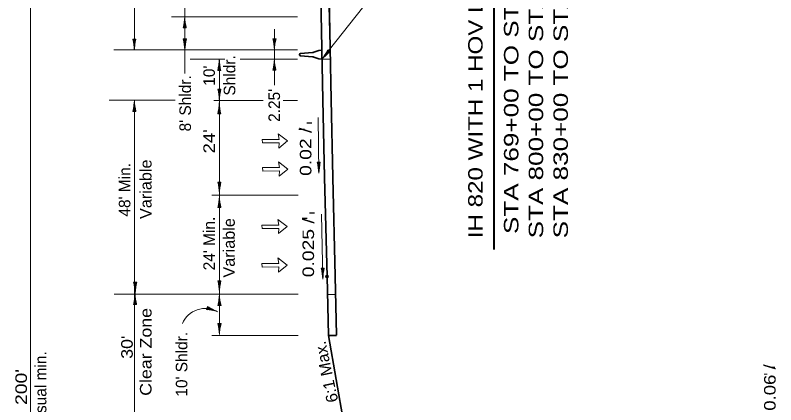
# Model space of a CAD drawing. Extents: x 2363427 to 2368559, y 6957299 to 6980140.
# Drawn here: x 2365734 to 2366656, y 6958581 to 6959053 of the extents above; entities that cross this region are included whole.
import ezdxf
from ezdxf.enums import TextEntityAlignment as Align

# ---------------------------------------------------------------- set-up
doc = ezdxf.new("R2010")
doc.units = 0
doc.header["$LTSCALE"] = 5.6
doc.header["$PDMODE"] = 32
doc.header["$PDSIZE"] = 2.8
for name, color, linetype, lineweight in [('3', 7, 'Continuous', 35), ('4', 7, 'Continuous', 13), ('40', 7, 'Continuous', 35), ('48', 7, 'Continuous', 25), ('8', 7, 'Continuous', 13)]:
    doc.layers.add(name, color=color, linetype=linetype, lineweight=lineweight)

msp = doc.modelspace()

# ---------------------------------------------------------------- linework, layer by layer
at = {"layer": '3'}
for p, q in [((2366104.162, 6959081.469), (2366106.765, 6958950.986)), ((2366114.16, 6959081.669), (2366116.764, 6958951.188)), ((2366078.416, 6959005.99), (2366078.416, 6959005.589)), ((2366078.416, 6959005.189), (2366078.416, 6959005.589)), ((2366094.146, 6959008.066), (2366079.442, 6959006.831)), ((2366094.146, 6959003.113), (2366079.442, 6959004.348)), ((2366095.934, 6959008.595), (2366102.048, 6959010.637)), ((2366102.212, 6959010.701), (2366102.222, 6959010.727)), ((2366105.486, 6959011.215), (2366102.222, 6959010.727)), ((2366105.486, 6959011.215), (2366102.42, 6959010.755)), ((2366105.486, 6959011.215), (2366105.486, 6959005.589)), ((2366105.486, 6958999.965), (2366105.486, 6959005.589)), ((2366095.934, 6959002.584), (2366102.048, 6959000.543)), ((2366102.212, 6959000.477), (2366102.222, 6959000.453)), ((2366105.486, 6958999.965), (2366102.222, 6959000.453)), ((2366105.486, 6958999.965), (2366102.42, 6959000.423)), ((2366106.78, 6958951.041), (2366108.665, 6958856.561)), ((2366116.781, 6958951.131), (2366118.664, 6958856.761)), ((2366108.665, 6958856.561), (2366111.798, 6958736.695)), ((2366118.662, 6958856.823), (2366121.794, 6958736.957)), ((2366111.798, 6958736.695), (2366113.463, 6958665.265)), ((2366121.795, 6958736.929), (2366123.464, 6958665.381)), ((2366123.466, 6958665.265), (2366113.463, 6958665.265)), ((2366113.463, 6958665.265), (2366176.398, 6958303.17))]:
    msp.add_line(p, q, dxfattribs=at)
at = {"layer": '3', "lineweight": 13}
for points in [[(2366105.835, 6959000.013), (2366115.77, 6958999.969), (2366113.701, 6959081.337), (2366115.727, 6959163.264), (2366105.486, 6959163.445), (2366104.058, 6959081.858)], [(2366112.317, 6958715.011), (2366122.339, 6958714.983), (2366115.77, 6958999.969), (2366105.835, 6959000.013)], [(2366113.463, 6958665.265), (2366123.464, 6958665.381), (2366122.339, 6958714.983), (2366112.317, 6958715.011)]]:
    msp.add_lwpolyline(points, close=True, dxfattribs=at)
msp.add_lwpolyline([(2366111.798, 6958736.695), (2366111.728, 6958736.841), (2366111.798, 6958736.695)], dxfattribs=at)
at = {"layer": '3'}
for centre, radius, start, end in [((2366079.563, 6959005.637), 1.2, 95.72178, 162.90786), ((2366079.563, 6959005.542), 1.2, 197.09214, 264.27822), ((2366093.647, 6959013.041), 5, 275.73538, 297.22872), ((2366093.647, 6958998.137), 5, 62.77128, 84.26462), ((2366102.597, 6959009.569), 1.2, 98.51269, 117.22516), ((2366102.597, 6959001.61), 1.2, 242.77484, 261.48731)]:
    msp.add_arc(centre, radius, start, end, dxfattribs=at)
msp.add_point((2366111.798, 6958736.695), dxfattribs=at)
at = {"layer": '4', "lineweight": 40}
msp.add_line((2366314.4, 6958769.555), (2366314.4, 6959504.227), dxfattribs=at)
at = {"layer": '4'}
for p, q in [((2365939.414, 6958982.729), (2365939.414, 6959175.239)), ((2365878.168, 6959010.933), (2365878.168, 6959151.469)), ((2366190.274, 6959107.231), (2366105.486, 6958999.965)), ((2365752.334, 6958047.045), (2365752.334, 6959081.469)), ((2366076.05, 6959051.469), (2365923.218, 6959051.469)), ((2365939.357, 6959038.088), (2365939.357, 6959050.652)), ((2365937.857, 6959038.088), (2365937.857, 6959040.469)), ((2365938.357, 6959038.088), (2365938.357, 6959042.95)), ((2365938.857, 6959038.088), (2365938.857, 6959046.697)), ((2365939.857, 6959038.088), (2365939.857, 6959045.438)), ((2365940.357, 6959038.088), (2365940.357, 6959042.365)), ((2365940.857, 6959038.088), (2365940.857, 6959039.673)), ((2365941.207, 6959038.088), (2365937.377, 6959038.088)), ((2366048.061, 6958968.593), (2366048.061, 6959036.385)), ((2365876.253, 6959024.237), (2365880.083, 6959024.237)), ((2365876.603, 6959024.237), (2365876.603, 6959022.651)), ((2365877.103, 6959024.237), (2365877.103, 6959019.96)), ((2365877.603, 6959024.237), (2365877.603, 6959016.887)), ((2365878.103, 6959024.237), (2365878.103, 6959011.673)), ((2365878.603, 6959024.237), (2365878.603, 6959015.627)), ((2365879.103, 6959024.237), (2365879.103, 6959019.375)), ((2365879.603, 6959024.237), (2365879.603, 6959021.855)), ((2365937.446, 6959024.614), (2365941.276, 6959024.614)), ((2365937.796, 6959024.614), (2365937.796, 6959023.029)), ((2365938.296, 6959024.614), (2365938.296, 6959020.337)), ((2365938.796, 6959024.614), (2365938.796, 6959017.264)), ((2365939.296, 6959024.614), (2365939.296, 6959012.05)), ((2365939.796, 6959024.614), (2365939.796, 6959016.005)), ((2365940.296, 6959024.614), (2365940.296, 6959019.752)), ((2365940.796, 6959024.614), (2365940.796, 6959022.233)), ((2366046.144, 6959024.896), (2366049.974, 6959024.896)), ((2366046.494, 6959024.896), (2366046.494, 6959023.311)), ((2366046.994, 6959024.896), (2366046.994, 6959020.619)), ((2366047.494, 6959024.896), (2366047.494, 6959017.546)), ((2366047.994, 6959024.896), (2366047.994, 6959012.332)), ((2366048.494, 6959024.896), (2366048.494, 6959016.287)), ((2366048.994, 6959024.896), (2366048.994, 6959020.034)), ((2366049.494, 6959024.896), (2366049.494, 6959022.515)), ((2366076.05, 6959011.469), (2365853.324, 6959011.469)), ((2366114.109, 6959010.107), (2366106.018, 6959000.495)), ((2366113.726, 6959010.429), (2366108.182, 6959003.842)), ((2366114.491, 6959009.784), (2366109.759, 6959004.162)), ((2366113.344, 6959010.751), (2366110.212, 6959007.031)), ((2366112.961, 6959011.073), (2366111.427, 6959009.251)), ((2366114.874, 6959009.462), (2366112.12, 6959006.191)), ((2366115.524, 6959008.914), (2366112.594, 6959011.382)), ((2366115.256, 6959009.14), (2366114.236, 6959007.928)), ((2365987.958, 6959000.219), (2365945.87, 6959000.219)), ((2365980.758, 6958986.495), (2365980.758, 6958995.105)), ((2365981.258, 6958986.495), (2365981.258, 6958999.059)), ((2365981.758, 6958986.495), (2365981.758, 6958993.845)), ((2366076.05, 6959000.219), (2366006.36, 6959000.219)), ((2366047.57, 6958986.668), (2366047.57, 6958995.277)), ((2366048.07, 6958986.668), (2366048.07, 6958999.232)), ((2366048.57, 6958986.668), (2366048.57, 6958994.018)), ((2365983.108, 6958986.495), (2365979.278, 6958986.495)), ((2365979.758, 6958986.495), (2365979.758, 6958988.877)), ((2365980.258, 6958986.495), (2365980.258, 6958991.357)), ((2365981.308, 6958855.697), (2365981.308, 6958988.947)), ((2365982.258, 6958986.495), (2365982.258, 6958990.771)), ((2365982.758, 6958986.495), (2365982.758, 6958988.08)), ((2366049.92, 6958986.668), (2366046.09, 6958986.668)), ((2366046.57, 6958986.668), (2366046.57, 6958989.049)), ((2366047.07, 6958986.668), (2366047.07, 6958991.53)), ((2366049.07, 6958986.668), (2366049.07, 6958990.945)), ((2366049.57, 6958986.668), (2366049.57, 6958988.253)), ((2365979.346, 6958963.955), (2365983.176, 6958963.955)), ((2365979.696, 6958963.955), (2365979.696, 6958962.37)), ((2365980.196, 6958963.955), (2365980.196, 6958959.679)), ((2365980.696, 6958963.955), (2365980.696, 6958956.605)), ((2365981.196, 6958963.955), (2365981.196, 6958951.391)), ((2365981.696, 6958963.955), (2365981.696, 6958955.345)), ((2365982.196, 6958963.955), (2365982.196, 6958959.093)), ((2365982.696, 6958963.955), (2365982.696, 6958961.573)), ((2365927.658, 6958950.457), (2365847.726, 6958950.457)), ((2365878.168, 6958949.718), (2365878.168, 6958312.003)), ((2365878.256, 6958936.843), (2365878.256, 6958949.407)), ((2366034.538, 6958950.219), (2365974.544, 6958950.219)), ((2366076.05, 6958950.219), (2366058.691, 6958950.219)), ((2365876.756, 6958936.843), (2365876.756, 6958939.225)), ((2365877.256, 6958936.843), (2365877.256, 6958941.705)), ((2365877.756, 6958936.843), (2365877.756, 6958945.453)), ((2365878.756, 6958936.843), (2365878.756, 6958944.193)), ((2365879.256, 6958936.843), (2365879.256, 6958941.119)), ((2365879.756, 6958936.843), (2365879.756, 6958938.428)), ((2365980.258, 6958933.701), (2365980.258, 6958938.563)), ((2365980.758, 6958933.701), (2365980.758, 6958942.311)), ((2365981.258, 6958933.701), (2365981.258, 6958946.265)), ((2365981.758, 6958933.701), (2365981.758, 6958941.051)), ((2365880.106, 6958936.843), (2365876.276, 6958936.843)), ((2365983.108, 6958933.701), (2365979.278, 6958933.701)), ((2365979.758, 6958933.701), (2365979.758, 6958936.083)), ((2365982.258, 6958933.701), (2365982.258, 6958937.978)), ((2365982.758, 6958933.701), (2365982.758, 6958935.287)), ((2366101.943, 6958861.886), (2366100.869, 6958929.603)), ((2366099.817, 6958875.165), (2366103.646, 6958875.226)), ((2366099.817, 6958875.165), (2366103.646, 6958875.226)), ((2366100.167, 6958875.171), (2366100.192, 6958873.586)), ((2366100.167, 6958875.171), (2366100.192, 6958873.586)), ((2366100.667, 6958875.179), (2366100.735, 6958870.903)), ((2366100.667, 6958875.179), (2366100.735, 6958870.903)), ((2366101.167, 6958875.187), (2366101.284, 6958867.838)), ((2366101.167, 6958875.187), (2366101.284, 6958867.838)), ((2366101.667, 6958875.195), (2366101.866, 6958862.632)), ((2366101.667, 6958875.195), (2366101.866, 6958862.632)), ((2366102.167, 6958875.203), (2366102.304, 6958866.594)), ((2366102.167, 6958875.203), (2366102.304, 6958866.594)), ((2366102.666, 6958875.211), (2366102.744, 6958870.349)), ((2366102.666, 6958875.211), (2366102.744, 6958870.349)), ((2366103.166, 6958875.219), (2366103.204, 6958872.837)), ((2366103.166, 6958875.219), (2366103.204, 6958872.837)), ((2365981.308, 6958736.492), (2365981.308, 6958855.697)), ((2365979.394, 6958850.955), (2365983.224, 6958850.955)), ((2365979.744, 6958850.955), (2365979.744, 6958849.371)), ((2365980.244, 6958850.955), (2365980.244, 6958846.679)), ((2365980.744, 6958850.955), (2365980.744, 6958843.605)), ((2365981.244, 6958850.955), (2365981.244, 6958838.391)), ((2365981.744, 6958850.955), (2365981.744, 6958842.346)), ((2365982.244, 6958850.955), (2365982.244, 6958846.093)), ((2365982.744, 6958850.955), (2365982.744, 6958848.574)), ((2366076.963, 6958835.265), (2365972.056, 6958835.265)), ((2365980.874, 6958820.271), (2365980.874, 6958828.881)), ((2365981.374, 6958820.271), (2365981.374, 6958832.835)), ((2365981.874, 6958820.271), (2365981.874, 6958827.621)), ((2365983.224, 6958820.271), (2365979.394, 6958820.271)), ((2365979.874, 6958820.271), (2365979.874, 6958822.653)), ((2365980.374, 6958820.271), (2365980.374, 6958825.133)), ((2365982.374, 6958820.271), (2365982.374, 6958824.547)), ((2365982.874, 6958820.271), (2365982.874, 6958821.856)), ((2366106.775, 6958733.419), (2366105.164, 6958812.039)), ((2366104.588, 6958746.689), (2366108.417, 6958746.767)), ((2366104.588, 6958746.689), (2366108.417, 6958746.767)), ((2366104.938, 6958746.695), (2366104.97, 6958745.111)), ((2366104.938, 6958746.695), (2366104.97, 6958745.111)), ((2366105.438, 6958746.706), (2366105.525, 6958742.431)), ((2366105.438, 6958746.706), (2366105.525, 6958742.431)), ((2366105.938, 6958746.716), (2366106.088, 6958739.368)), ((2366105.938, 6958746.716), (2366106.088, 6958739.368)), ((2366106.437, 6958746.727), (2366106.694, 6958734.165)), ((2366106.437, 6958746.727), (2366106.694, 6958734.165)), ((2366106.937, 6958746.737), (2366107.114, 6958738.129)), ((2366106.937, 6958746.737), (2366107.114, 6958738.129)), ((2366107.437, 6958746.747), (2366107.536, 6958741.886)), ((2366107.437, 6958746.747), (2366107.536, 6958741.886)), ((2366107.937, 6958746.757), (2366107.986, 6958744.376)), ((2366107.937, 6958746.757), (2366107.986, 6958744.376)), ((2365981.366, 6958675.787), (2365981.366, 6958736.515)), ((2365877.261, 6958729.965), (2365881.091, 6958729.965)), ((2365877.611, 6958729.965), (2365877.611, 6958728.379)), ((2365878.111, 6958729.965), (2365878.111, 6958725.688)), ((2365878.611, 6958729.965), (2365878.611, 6958722.615)), ((2365879.111, 6958729.965), (2365879.111, 6958717.401)), ((2365879.611, 6958729.965), (2365879.611, 6958721.355)), ((2365880.111, 6958729.965), (2365880.111, 6958725.103)), ((2365880.611, 6958729.965), (2365880.611, 6958727.583)), ((2365979.394, 6958731.299), (2365983.224, 6958731.299)), ((2365979.744, 6958731.299), (2365979.744, 6958729.715)), ((2365980.244, 6958731.299), (2365980.244, 6958727.023)), ((2365980.744, 6958731.299), (2365980.744, 6958723.949)), ((2365981.244, 6958731.299), (2365981.244, 6958718.735)), ((2365981.744, 6958731.299), (2365981.744, 6958722.69)), ((2365982.244, 6958731.299), (2365982.244, 6958726.437)), ((2365982.744, 6958731.299), (2365982.744, 6958728.918)), ((2366076.963, 6958715.265), (2365853.566, 6958715.265)), ((2365878.64, 6958702.771), (2365878.64, 6958711.381)), ((2365879.14, 6958702.771), (2365879.14, 6958715.335)), ((2365879.64, 6958702.771), (2365879.64, 6958710.121)), ((2365980.93, 6958701.54), (2365980.93, 6958710.149)), ((2365981.43, 6958701.54), (2365981.43, 6958714.104)), ((2365981.93, 6958701.54), (2365981.93, 6958708.89)), ((2365880.99, 6958702.771), (2365877.16, 6958702.771)), ((2365877.64, 6958702.771), (2365877.64, 6958705.153)), ((2365878.14, 6958702.771), (2365878.14, 6958707.633)), ((2365880.14, 6958702.771), (2365880.14, 6958707.048)), ((2365880.64, 6958702.771), (2365880.64, 6958704.357)), ((2365965.679, 6958696.608), (2365966.844, 6958700.257)), ((2365966.394, 6958698.847), (2365974.596, 6958696.227)), ((2365966.546, 6958699.323), (2365971.178, 6958697.843)), ((2365966.698, 6958699.799), (2365968.967, 6958699.075)), ((2365983.28, 6958701.54), (2365979.45, 6958701.54)), ((2365979.93, 6958701.54), (2365979.93, 6958703.921)), ((2365980.43, 6958701.54), (2365980.43, 6958706.402)), ((2365982.43, 6958701.54), (2365982.43, 6958705.817)), ((2365982.93, 6958701.54), (2365982.93, 6958703.125)), ((2365965.786, 6958696.941), (2365967.296, 6958696.459)), ((2365965.938, 6958697.418), (2365970.012, 6958696.117)), ((2365966.09, 6958697.894), (2365973.091, 6958695.657)), ((2365966.242, 6958698.371), (2365978.21, 6958694.547)), ((2365979.45, 6958679.517), (2365983.28, 6958679.517)), ((2365979.8, 6958679.517), (2365979.8, 6958677.933)), ((2365980.3, 6958679.517), (2365980.3, 6958675.241)), ((2365980.8, 6958679.517), (2365980.8, 6958672.167)), ((2365981.3, 6958679.517), (2365981.3, 6958666.953)), ((2365981.8, 6958679.517), (2365981.8, 6958670.908)), ((2365982.3, 6958679.517), (2365982.3, 6958674.655)), ((2365982.8, 6958679.517), (2365982.8, 6958677.136)), ((2366076.823, 6958665.265), (2365972.056, 6958665.265))]:
    msp.add_line(p, q, dxfattribs=at)
at = {"layer": '4', "lineweight": 25}
for p, q in [((2366087.275, 6958923.005), (2366093.229, 6958923.005)), ((2366084.298, 6958914.93), (2366077.494, 6958914.93)), ((2366090.684, 6958813.831), (2366096.637, 6958813.831)), ((2366087.707, 6958807.032), (2366081.753, 6958807.032))]:
    msp.add_line(p, q, dxfattribs=at)
at = {"layer": '4'}
for centre, radius, start, end in [((2365867.168, 6959054.982), 72.212, 346.47039, 357.15644), ((2366011.415, 6959054.982), 72.212, 182.84356, 193.52961), ((2365806.044, 6959007.342), 72.212, 2.84356, 13.52961), ((2365950.291, 6959007.342), 72.212, 166.47039, 177.15644), ((2365867.237, 6959007.72), 72.212, 2.84356, 13.52961), ((2366011.485, 6959007.72), 72.212, 166.47039, 177.15644), ((2365975.935, 6959008.002), 72.212, 2.84356, 13.52961), ((2366120.182, 6959008.002), 72.212, 166.47039, 177.15644), ((2366048.005, 6959043.675), 72.212, 322.74962, 333.43567), ((2366158.353, 6958950.774), 72.212, 126.37646, 137.06251), ((2365909.069, 6959003.389), 72.212, 346.47039, 357.15644), ((2366053.317, 6959003.389), 72.212, 182.84356, 193.52961), ((2365975.88, 6959003.562), 72.212, 346.47039, 357.15644), ((2366120.127, 6959003.562), 72.212, 182.84356, 193.52961), ((2365909.137, 6958947.061), 72.212, 2.84356, 13.52961), ((2366053.384, 6958947.061), 72.212, 166.47039, 177.15644), ((2365806.067, 6958953.737), 72.212, 346.47039, 357.15644), ((2365950.315, 6958953.737), 72.212, 182.84356, 193.52961), ((2365909.069, 6958950.595), 72.212, 346.47039, 357.15644), ((2366053.317, 6958950.595), 72.212, 182.84356, 193.52961), ((2366029.885, 6958857.16), 72.212, 3.7522, 14.43825), ((2366029.885, 6958857.16), 72.212, 3.7522, 14.43825), ((2366174.114, 6958859.448), 72.212, 167.37903, 178.06508), ((2366174.114, 6958859.448), 72.212, 167.37903, 178.06508), ((2365909.185, 6958834.062), 72.212, 2.84356, 13.52961), ((2366053.432, 6958834.062), 72.212, 166.47039, 177.15644), ((2365909.185, 6958837.165), 72.212, 346.47039, 357.15644), ((2366053.432, 6958837.165), 72.212, 182.84356, 193.52961), ((2366034.74, 6958728.36), 72.212, 4.01743, 14.70348), ((2366034.74, 6958728.36), 72.212, 4.01743, 14.70348), ((2366178.957, 6958731.315), 72.212, 167.64427, 178.33032), ((2366178.957, 6958731.315), 72.212, 167.64427, 178.33032), ((2365807.052, 6958713.071), 72.212, 2.84356, 13.52961), ((2365951.3, 6958713.071), 72.212, 166.47039, 177.15644), ((2365909.185, 6958714.406), 72.212, 2.84356, 13.52961), ((2366053.432, 6958714.406), 72.212, 166.47039, 177.15644), ((2365806.952, 6958719.665), 72.212, 346.47039, 357.15644), ((2365951.199, 6958719.665), 72.212, 182.84356, 193.52961), ((2365909.242, 6958718.434), 72.212, 346.47039, 357.15644), ((2366053.489, 6958718.434), 72.212, 182.84356, 193.52961), ((2366004.303, 6958761.994), 72.212, 238.75343, 249.43948), ((2365963.922, 6958668.319), 29.635, 59.62074, 157.81619), ((2365960.406, 6958624.588), 72.212, 75.12659, 85.81264), ((2365909.242, 6958662.624), 72.212, 2.84356, 13.52961), ((2366053.489, 6958662.624), 72.212, 166.47039, 177.15644)]:
    msp.add_arc(centre, radius, start, end, dxfattribs=at)
at = {"layer": '40', "lineweight": 13}
for p, q in [((2366053.875, 6958898.728), (2366033.37, 6958898.533)), ((2366054.269, 6958864.763), (2366033.764, 6958864.567)), ((2366053.481, 6958794.99), (2366032.976, 6958794.795)), ((2366053.481, 6958748.363), (2366032.976, 6958748.168))]:
    msp.add_line(p, q, dxfattribs=at)
for points in [[(2366053.838, 6958902.823), (2366033.332, 6958902.628), (2366033.37, 6958898.533)], [(2366053.875, 6958898.728), (2366053.342, 6958892.413), (2366063.73, 6958900.948), (2366052.63, 6958909.551), (2366053.838, 6958902.823)], [(2366054.269, 6958864.763), (2366053.736, 6958858.447), (2366064.124, 6958866.983), (2366053.024, 6958875.585), (2366054.232, 6958868.857)], [(2366054.232, 6958868.857), (2366033.726, 6958868.663), (2366033.764, 6958864.567)], [(2366053.481, 6958794.99), (2366052.948, 6958788.675), (2366063.336, 6958797.21), (2366052.236, 6958805.813), (2366053.444, 6958799.085)], [(2366053.444, 6958799.085), (2366032.938, 6958798.89), (2366032.976, 6958794.795)], [(2366053.481, 6958748.363), (2366052.948, 6958742.048), (2366063.336, 6958750.583), (2366052.236, 6958759.185), (2366053.444, 6958752.458)], [(2366053.444, 6958752.458), (2366032.938, 6958752.263), (2366032.976, 6958748.168)]]:
    msp.add_lwpolyline(points, dxfattribs=at)
at = {"layer": '48', "lineweight": 13}
for p, q in [((2366650.862, 6958626.596), (2366654.652, 6958626.596)), ((2366641.598, 6958618.18), (2366645.388, 6958618.18))]:
    msp.add_line(p, q, dxfattribs=at)
at = {"layer": '8'}
for points in [[(2366063.73, 6958900.948), (2366053.342, 6958892.413), (2366053.875, 6958898.728), (2366033.37, 6958898.533), (2366033.332, 6958902.628), (2366053.838, 6958902.823), (2366052.63, 6958909.551)], [(2366064.124, 6958866.983), (2366053.736, 6958858.447), (2366054.269, 6958864.763), (2366033.764, 6958864.567), (2366033.726, 6958868.663), (2366054.232, 6958868.857), (2366053.024, 6958875.585)], [(2366063.336, 6958797.21), (2366052.948, 6958788.675), (2366053.481, 6958794.99), (2366032.976, 6958794.795), (2366032.938, 6958798.89), (2366053.444, 6958799.085), (2366052.236, 6958805.813)], [(2366063.336, 6958750.583), (2366052.948, 6958742.048), (2366053.481, 6958748.363), (2366032.976, 6958748.168), (2366032.938, 6958752.263), (2366053.444, 6958752.458), (2366052.236, 6958759.185)]]:
    msp.add_lwpolyline(points, close=True, dxfattribs=at)

# ---------------------------------------------------------------- texts
at = {"layer": '4'}
for s, height, rotation, width, p in [('IH 820 WITH 1 HOV LANE AND FRONTAGE ROADS', 17.5, 90, 1.25, (2366300.428, 6959134.194)), ('STA 769+00 TO STA 786+00 ', 17.5, 90, 1.35, (2366343.81, 6958999.815)), ('STA 800+00 TO STA 830+00', 17.5, 90, 1.35, (2366373.81, 6958990.166)), ('STA 830+00 TO STA 835+60', 17.5, 90, 1.35, (2366403.81, 6958990.166)), ("24'", 14, 90, 1.2, (2365975.833, 6958900.51)), ('0.02 /', 14, 90, 1.25, (2366092.836, 6958887.882)), ('Variable', 14, 90, 1.05, (2365898.982, 6958842.435)), ('Variable', 14, 90, 1.05, (2365999.943, 6958771.383)), ('0.025 /', 14, 90, 1.25, (2366096.058, 6958771.54)), ('Clear Zone', 14, 90, 1.15, (2365898.982, 6958645.286)), ("30'", 14, 90, 1.15, (2365876.216, 6958650.952)), ('6:1 Max.', 14, 101.975, 1.05, (2366117.669, 6958622.447)), ("200'", 14, 90, 1.25, (2365747.951, 6958602.742))]:
    msp.add_text(s, height=height, rotation=rotation, dxfattribs=dict(at, width=width)).set_placement(p, align=Align.CENTER)
for s, p in [('Shldr.', (2366000.566, 6958980.439)), ("10'", (2365975.833, 6958980.115)), ("8' Shldr.", (2365946.838, 6958946.59)), ("2.25' ", (2366054.786, 6958946.692)), ("48' Min.", (2365873.366, 6958841.77)), ("24' Min.", (2365975.833, 6958776.655)), ("10' Shldr.", (2365942.446, 6958630.251)), ('Usual min.', (2365771.551, 6958601.81))]:
    msp.add_text(s, height=14, rotation=90, dxfattribs=at).set_placement(p, align=Align.CENTER)
at = {"layer": '4', "width": 1.2}
msp.add_text('2. MAXIMUM SUPERELEVATION RATE= 0.06 /', height=14, rotation=90, dxfattribs=at).set_placement((2366655.664, 6958145.154))

doc.saveas('drawing.dxf')
